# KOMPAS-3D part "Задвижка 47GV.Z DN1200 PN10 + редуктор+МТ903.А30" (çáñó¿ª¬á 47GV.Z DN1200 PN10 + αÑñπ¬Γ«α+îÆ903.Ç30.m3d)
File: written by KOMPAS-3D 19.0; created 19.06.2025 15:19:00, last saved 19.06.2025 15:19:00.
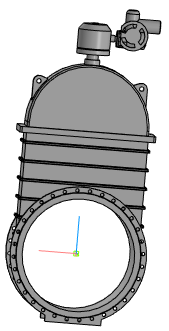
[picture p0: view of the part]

Document properties: Полное имя файла: Задвижка 47GV.Z DN1200 PN10 + редуктор+МТ903.А30.a3d

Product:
- Part/product: Задвижка 47GV.Z DN1200 PN10 + редуктор+МТ903.А30
    Масса: 6623.9

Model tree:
1. Операция без истории:1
